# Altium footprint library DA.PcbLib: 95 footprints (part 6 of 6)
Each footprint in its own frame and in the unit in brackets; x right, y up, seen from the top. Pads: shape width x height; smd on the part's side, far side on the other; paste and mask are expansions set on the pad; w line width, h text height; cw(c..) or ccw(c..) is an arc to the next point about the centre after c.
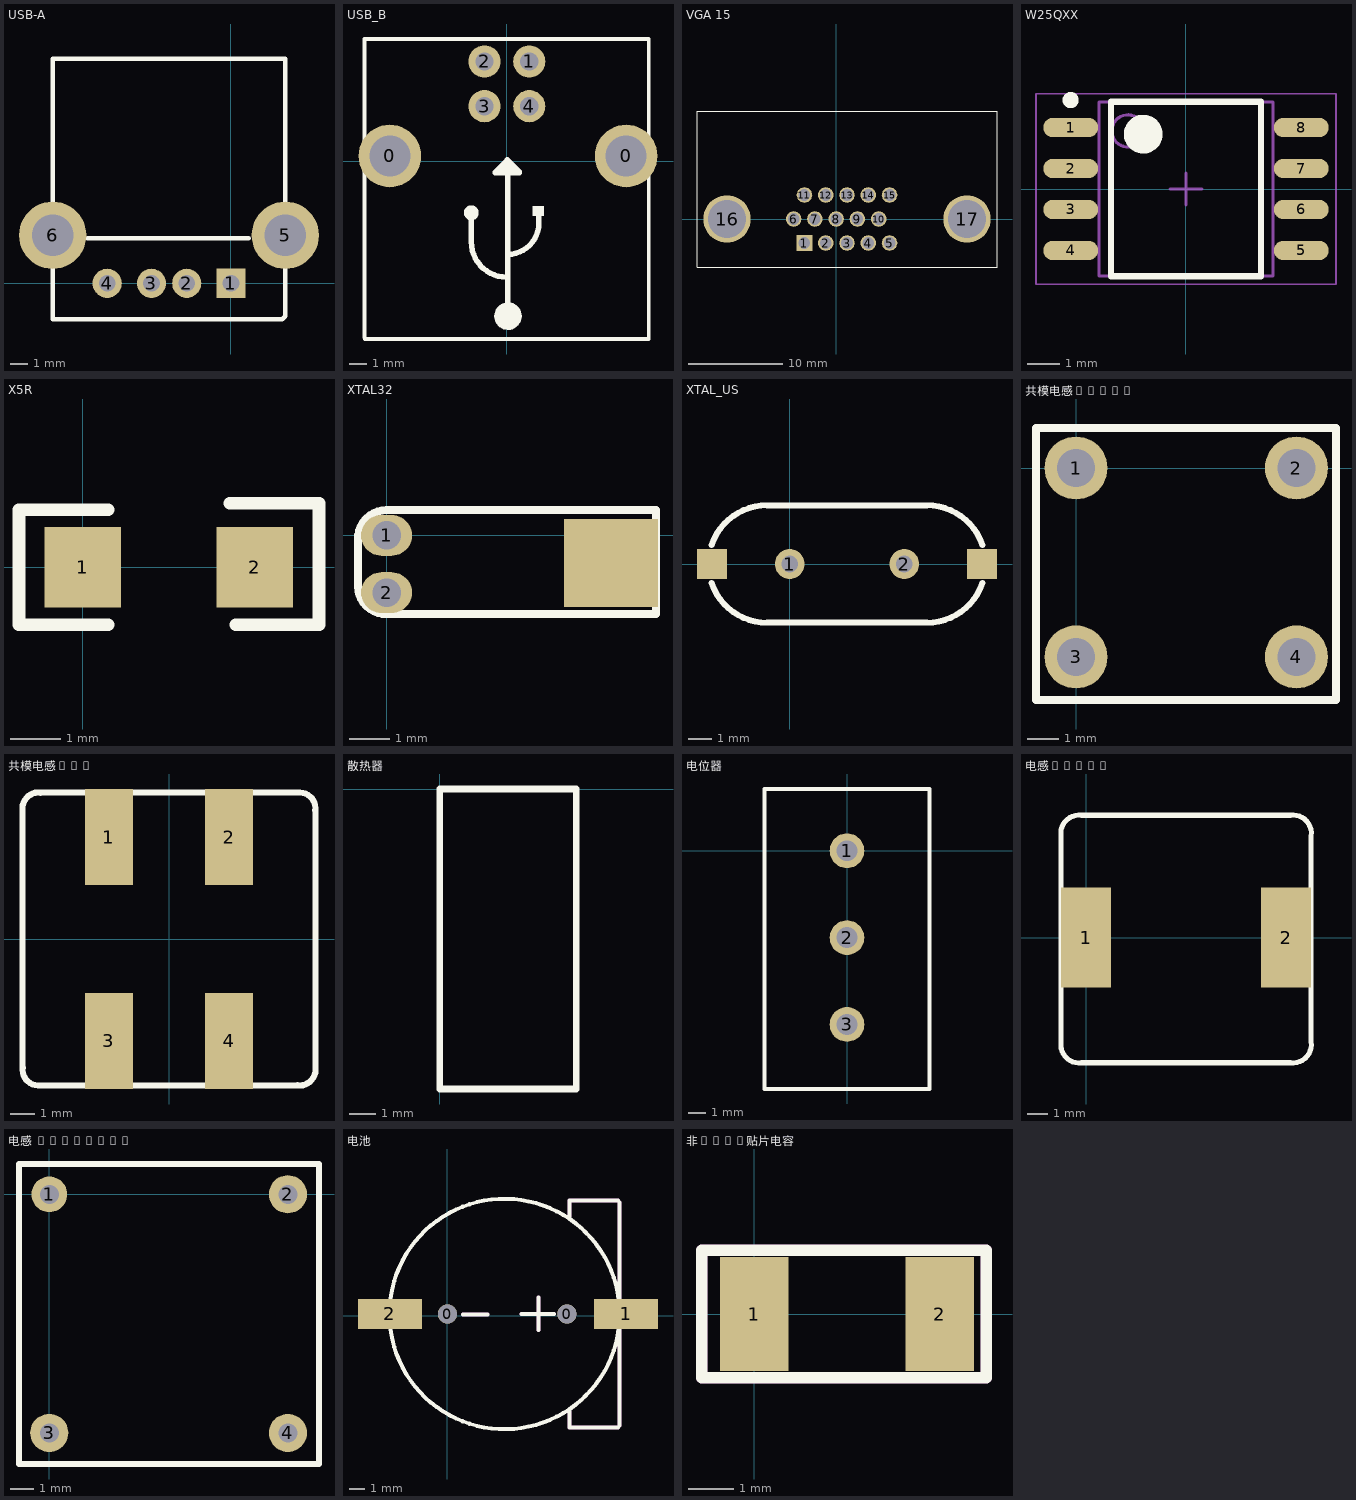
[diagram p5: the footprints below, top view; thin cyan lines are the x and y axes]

## USB-A [mil]
pads (6):
  rect 65x65 hole 37: 1(0,0)
  round 65 hole 37: 2(-98.5,0) 3(-177,0) 4(-275.6,0)
  round 150 hole 93: 5(121,107) 6(-397,107)
Top Overlay:
  lines w10: -320,100 40,100 ; -397,-80 -397,107 -397,500 121,500 121,107 121,-73 114,-80 -397,-80
3D body: height 274.23, standoff -164.75, extent -449.02,-45 173.02,494.37

## USB_B [mm]
pads (6):
  round 3.5 hole 2.3: 0(-6.519,0.307) 0(6.681,0.307)
  round 1.8 hole 1.016: 1(1.27,5.588) 2(-1.23,5.588) 3(-1.23,3.088) 4(1.27,3.088)
Top Overlay:
  rectangle: 1.456,-3.043 2.106,-2.493
  rectangle: -2.069,-2.943 -1.869,-2.743
  rectangle: -0.244,-9.118 0.456,-8.168
  lines w0.203: -7.936,-9.844 -7.936,6.844 7.939,6.844 7.939,-9.92 ; -7.919,5.757 -7.919,-9.918 7.956,-9.918 7.956,5.757 ; -7.844,6.824 7.956,6.824
  lines w0.305: -1.969,-2.993 -1.969,-4.493 ccw(c0.006,-4.493) 0.006,-6.468 ; -1.755,-3.017 cw(c-1.969,-2.868) -1.719,-2.944 ; -0.644,-0.618 0.706,-0.618 0.456,-0.368 -0.369,-0.368 ; -0.619,-0.593 0.056,0.082 0.056,-8.393 ; -0.344,-8.318 ccw(c0.056,-8.568) -0.294,-8.252 ; -0.246,-8.119 ccw(c0.081,-8.643) -0.199,-8.093 ; 0.031,-0.168 0.031,0.107 0.706,-0.568 ; 0.056,-5.193 ccw(c0.056,-3.443) 1.806,-3.443 1.806,-3.093 ; 0.18,-8.391 ccw(c0.006,-8.518) 0.22,-8.491

## VGA 15 [mil]
pads (17):
  rect 65x65 hole 48: 1(-132.16,-100)
  round 65 hole 48: 2(-43.58,-100) 3(45,-100) 4(133.58,-100) 5(222.16,-100) 6(-177.17,0) 7(-88.58,0) 8(0,0) 9(88.58,0) 10(177.16,0) 11(-132.16,100) 12(-43.58,100) 13(45,100) 14(133.58,100) 15(222.16,100)
  round 196.85 hole 157.48: 16(-455,0) 17(545,0)
Top Overlay:
  lines w5: -580,-200 670,-200 670,450 -580,450 -580,-200

## W25QXX [mm] "SOIC, 8-Leads, Body 5.28x5.28mm, Pitch 1.27mm, IPC Medium Density"
height 2
pads (8):
  oval 1.7x0.6 smd: 1(-3.575,1.905) 2(-3.575,0.635) 3(-3.575,-0.635) 4(-3.575,-1.905) 5(3.575,-1.905) 6(3.575,-0.635) 7(3.575,0.635) 8(3.575,1.905)
Top Overlay:
  circle w0.6: c-1.325,1.7 r0.3
  circle w0.25: c-3.575,2.755 r0.125
  lines w0.2: -2.325,-2.7 2.325,-2.7 2.325,2.7 -2.325,2.7 -2.325,-2.7
Mechanical 13:
  circle w0.1: c-1.8,1.8 r0.5
  lines w0.1: -2.7,-2.7 2.7,-2.7 2.7,2.7 -2.7,2.7 -2.7,-2.7
Mechanical 15:
  lines w0.05: -4.65,-2.95 4.65,-2.95 4.65,2.95 -4.65,2.95 -4.65,-2.95
  lines w0.1: -0.5,0 0.5,0 ; 0,-0.5 0,0.5
3D body: height 2, standoff 0.1, extent -2.7,-2.7 2.7,2.7

## X5R [mm]
pads (2):
  rect 1.52x1.6 smd: 1(0,0) 2(3.42,0)
Top Overlay:
  lines w0.254: 0.508,-1.143 -1.27,-1.143 -1.27,1.143 -1.016,1.143 0.508,1.143 ; 2.921,1.27 4.699,1.27 4.699,-1.143 3.048,-1.143

## XTAL32 [mil]
pads (3):
  oval 50x40 hole 28: 1(0,0) 2(0,-56)
  rect 92.13x86 smd: ""(220,-27)
Top Overlay:
  lines w8: -28,-50 ccw(c-0.5,-49.5) 0,-77 264,-77 264,25 0,25 ccw(c0.5,-3.5) -28,-4 -28,-50

## XTAL_US [mil]
height 149.61
pads (4):
  round 50 hole 28: 1(0,0) 2(192.13,0)
  rect 50x50 smd: ""(-130.32,0) ""(322.44,0)
Top Overlay:
  lines w10: -130.92,-31.85 ccw(c-37.79,0) -37.79,-98.42 ; -130.92,31.85 cw(c-37.79,0) -37.79,98.43 ; -38,98.42 229.92,98.43 cw(c229.92,0) 323.05,31.85 ; -37.8,-98.43 229.92,-98.42 ccw(c229.92,0) 323.05,-31.85

## 共模电感150uH [mm]
pads (4):
  round 2 hole 1.2: 1(0,0) 2(7,0) 3(0,-6) 4(7,-6)
Top Overlay:
  lines w0.254: -1.27,-7.366 8.255,-7.366 8.255,1.27 -1.27,1.27 -1.27,-7.366

## 共模电感154 [mm]
pads (4):
  rect 2x4 smd: 1(-2.5,4.25) 2(2.5,4.25) 3(-2.5,-4.25) 4(2.5,-4.25)
Top Overlay:
  lines w0.254: -6.1,-5.457 -6.1,5.584 ; -6.087,-5.357 ccw(c-5.461,-5.461) -5.581,-6.085 ; -6.085,5.581 cw(c-5.461,5.461) -5.357,6.087 ; -5.584,6.1 -5.298,6.1 -5.294,6.096 5.461,6.096 ; -5.457,-6.1 5.584,-6.1 ; 5.357,-6.087 ccw(c5.461,-5.461) 6.085,-5.581 ; 5.581,6.085 cw(c5.461,5.461) 6.087,5.357 ; 6.1,-5.584 6.1,5.457

## 散热器 [mm]
Top Overlay:
  lines w0.254: 0,-11.176 5.08,-11.176 5.08,0 0,0 0,-11.176

## 电位器 [mm]
pads (3):
  round 2 hole 1.2: 1(0,0) 2(0,-5) 3(0,-10)
Top Overlay:
  lines w0.254: -4.75,3.5 -4.75,-13.5 -4.75,-13.716 4.75,-13.716 4.75,3.556 -4.75,3.556

## 电感12*12 [mm]
pads (2):
  rect 2.5x5 smd: 1(0,0) 2(10,0)
Top Overlay:
  lines w0.254: -1.25,-5.39 -1.25,5.088 cw(c-0.343,5.218) -0.224,6.126 10.22,6.126 cw(c10.35,5.219) 11.258,5.1 11.258,-5.215 cw(c10.351,-5.345) 10.232,-6.253 -0.212,-6.253 cw(c-0.342,-5.346) -1.25,-5.227

## 电感 18*10*10 [mm]
pads (4):
  round 1.5 hole 0.8: 1(0,0)
  round 1.6 hole 0.8: 2(10,0) 3(0,-10) 4(10,-10)
Top Overlay:
  lines w0.254: -1.27,-11.303 11.303,-11.303 11.303,1.27 -1.27,1.27 -1.27,-11.303

## 电池 [mm]
pads (4):
  round 1.2 hole 1.2: 0(0.009,0.113) 0(7.502,0.113)
  rect 4x1.9 smd: 1(11.21,0.113) 2(-3.597,0.113)
Top Overlay:
  circle w0.254: c3.59,0.113 r7.22
Top Overlay keep-out:
  lines w0.254: 0.993,0.069 2.517,0.069 ; 4.651,0.12 6.683,0.12 ; 5.718,-0.896 5.718,1.136 ; 7.654,-5.983 7.654,-6.999 10.702,-6.999 10.81,-6.89 10.81,0.113 10.81,7.117 10.702,7.225 7.654,7.225 7.654,6.209

## 非0805贴片电容 [mm]
pads (2):
  rect 1.5x2.5 smd: 1(0,0) 2(4.064,0)
Top Overlay keep-out:
  lines w0.254: -1.143,-1.397 -1.143,1.397 5.08,1.397 5.08,-1.397 -1.143,-1.397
